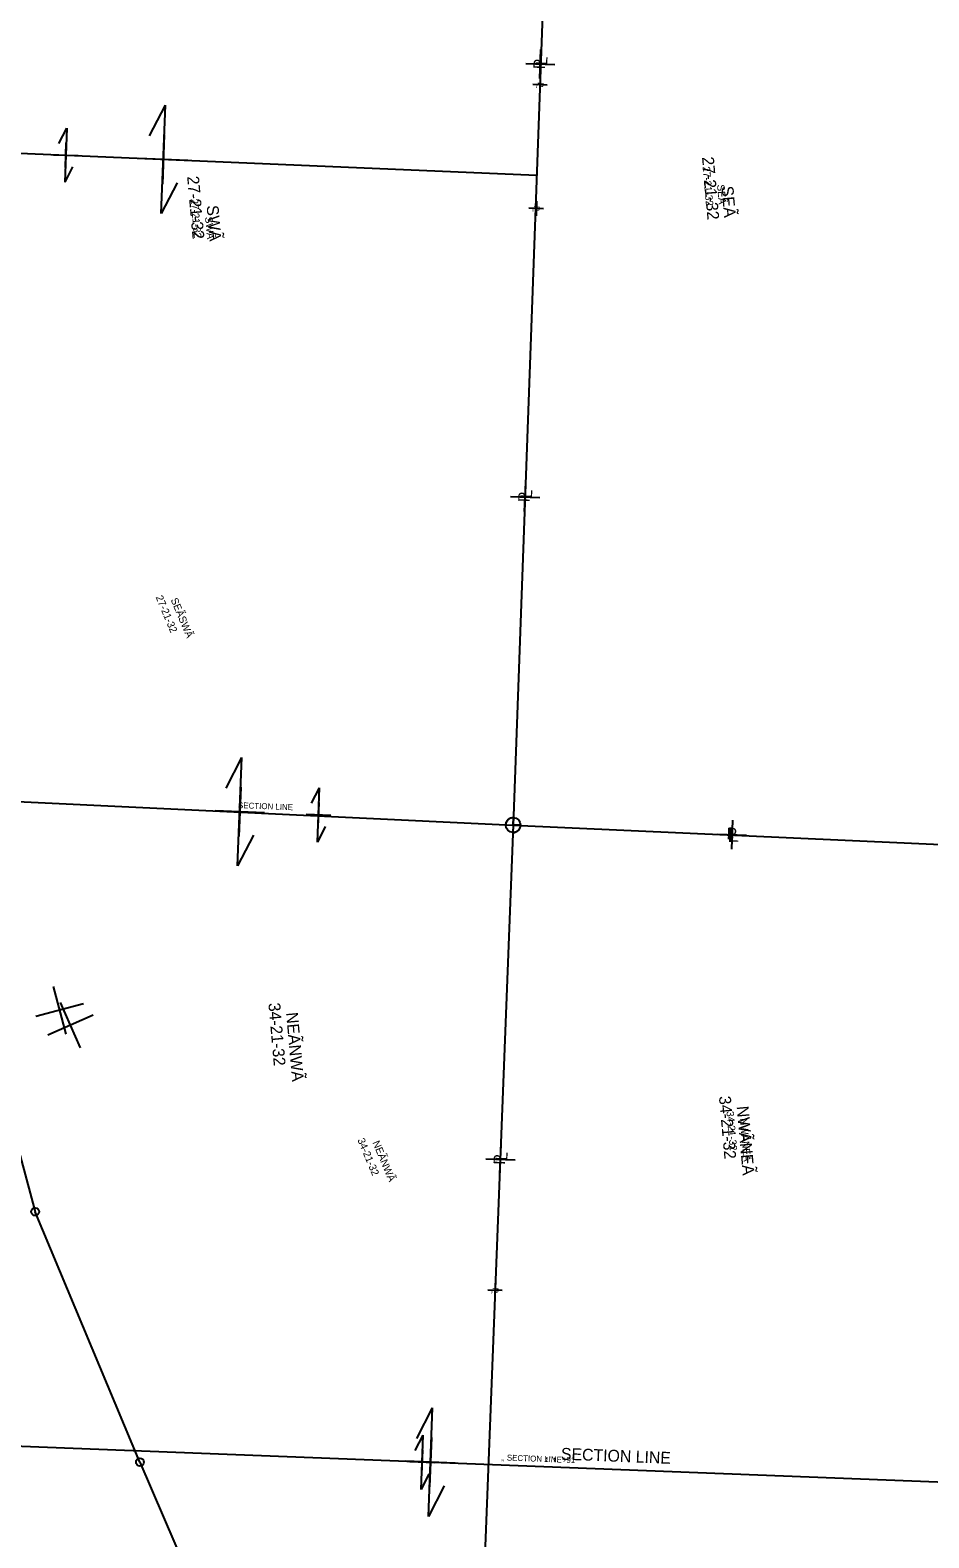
# Model space of a CAD drawing. Extents: x 2814293 to 2835768, y 121185 to 156337.
# Drawn here: x 2822119 to 2823940, y 124221 to 127276 of the extents above; entities that cross this region are included whole.
import ezdxf

# ---------------------------------------------------------------- set-up
doc = ezdxf.new("R2010")
doc.units = 0
for name, color, linetype in [('Default', 7, 'Continuous'), ('Photo-Retaining wall', 7, 'Continuous'), ('Roadway-Alignment notes', 7, 'Continuous'), ('Roadway-Edge of pavement', 7, 'Continuous'), ('Roadway-Edge of shoulder', 7, 'Continuous'), ('Roadway-Entrances', 7, 'Continuous'), ('Roadway-New rw', 7, 'Continuous'), ('Roadway-Safety', 7, 'Continuous'), ('Roadway-Walls', 7, 'Continuous'), ('Scratch-2', 7, 'Continuous'), ('Scratch-4', 7, 'Continuous'), ('Scratch-5', 7, 'Continuous'), ('Text-New rw label', 7, 'Continuous')]:
    doc.layers.add(name, color=color, linetype=linetype)

msp = doc.modelspace()

# ---------------------------------------------------------------- linework, layer by layer
at = {"layer": 'Default'}
for p, q in [((2822192, 125241.4), (2822166.3, 125338.1)), ((2822227.5, 125302.6), (2822130.8, 125276.9)), ((2822221.1, 125213.6), (2822181, 125305.3)), ((2822246.9, 125279.5), (2822155.2, 125239.4))]:
    msp.add_line(p, q, dxfattribs=at)
at = {"layer": 'Roadway-Edge of pavement'}
for p, q in [((2822177.4, 127046.3), (2822193.3, 127077.4)), ((2822193.3, 127077.4), (2822189.4, 126967.5)), ((2822190.5, 126997.5), (2822192.3, 127047.5)), ((2822166.4, 127023.4), (2822216.4, 127021.6)), ((2822191.4, 127022.5), (2822191.4, 127022.5)), ((2822205.3, 126998.7), (2822189.4, 126967.5)), ((2822689.5, 125709.4), (2822705.5, 125740.6)), ((2822701.3, 125630.6), (2822705.5, 125740.6)), ((2822704.4, 125710.6), (2822702.4, 125660.6)), ((2822728.4, 125684.6), (2822678.4, 125686.6)), ((2822703.4, 125685.6), (2822703.4, 125685.6)), ((2822717.3, 125661.8), (2822701.3, 125630.6)), ((2822899.5, 124397.6), (2822915.5, 124428.7)), ((2822911.2, 124318.8), (2822915.5, 124428.7)), ((2822914.3, 124398.8), (2822912.4, 124348.8)), ((2822938.3, 124372.8), (2822888.3, 124374.7)), ((2822913.3, 124373.8), (2822913.3, 124373.8)), ((2822927.2, 124349.9), (2822911.2, 124318.8))]:
    msp.add_line(p, q, dxfattribs=at)
at = {"layer": 'Roadway-Edge of shoulder'}
for p, q in [((2823152.1, 127177.9), (2823154.2, 127236.8)), ((2823123.7, 127208.4), (2823182.6, 127206.3)), ((2823121.2, 126300.5), (2823123.3, 126359.4)), ((2823092.8, 126331), (2823151.7, 126328.9)), ((2823542.3, 125674.8), (2823540, 125616)), ((2823511.7, 125646.6), (2823570.6, 125644.3)), ((2823071.2, 124958), (2823073.3, 125016.9)), ((2823042.8, 124988.5), (2823101.7, 124986.4))]:
    msp.add_line(p, q, dxfattribs=at)
at = {"layer": 'Roadway-Entrances'}
for p, q in [((2823193.2, 128299.4), (2823097.9, 125665)), ((2821815.2, 127038.4), (2823145.5, 126981.8)), ((2821766.3, 125728.5), (2823097.9, 125665)), ((2823097.9, 125665), (2822994.3, 122998.5)), ((2823097.9, 125665), (2825767.5, 125544.2)), ((2820377.3, 124472.9), (2825726, 124265.6))]:
    msp.add_line(p, q, dxfattribs=at)
at = {"layer": 'Roadway-New rw'}
for p, q in [((2822050.4, 125173.6), (2822129.4, 124881.4)), ((2822341.7, 124374.1), (2822129.4, 124881.4)), ((2822341.7, 124374.1), (2822651.5, 123652.3))]:
    msp.add_line(p, q, dxfattribs=at)
at = {"layer": 'Roadway-Walls'}
for p, q in [((2823167, 127164.4), (2823137.6, 127165.5)), ((2823152.8, 127179.7), (2823151.8, 127150.2)), ((2823145.2, 126929.3), (2823144.2, 126899.8)), ((2823159.4, 126914), (2823130, 126915.1)), ((2823522.6, 125646.1), (2823552, 125644.9)), ((2823537.9, 125660.2), (2823536.8, 125630.8)), ((2823075.9, 124721.5), (2823046.5, 124722.5)), ((2823061.7, 124736.7), (2823060.7, 124707.3))]:
    msp.add_line(p, q, dxfattribs=at)
at = {"layer": 'Scratch-2'}
for p, q in [((2822361.3, 127061.6), (2822393.3, 127123.8)), ((2822384.8, 126904), (2822393.3, 127123.8)), ((2822391, 127063.9), (2822387.1, 126964)), ((2822439, 127012), (2822339.1, 127015.9)), ((2822389.1, 127013.9), (2822389.1, 127013.9)), ((2822416.8, 126966.3), (2822384.8, 126904)), ((2822516.1, 125739.5), (2822548.1, 125801.8)), ((2822539.6, 125582), (2822548.1, 125801.8)), ((2822545.8, 125741.8), (2822541.9, 125641.9)), ((2822593.8, 125689.9), (2822493.9, 125693.8)), ((2822543.9, 125691.9), (2822543.9, 125691.9)), ((2822571.6, 125644.2), (2822539.6, 125582)), ((2822179.1, 125289.8), (2822179.1, 125289.8)), ((2822201.1, 125259.4), (2822201.1, 125259.4)), ((2822902.6, 124421.6), (2822934.6, 124483.8)), ((2822926.1, 124264), (2822934.6, 124483.8)), ((2822932.3, 124423.8), (2822928.4, 124323.9)), ((2822980.3, 124371.9), (2822880.4, 124375.8)), ((2822930.4, 124373.9), (2822930.4, 124373.9)), ((2822958.1, 124326.2), (2822926.1, 124264))]:
    msp.add_line(p, q, dxfattribs=at)
at = {"layer": 'Scratch-4'}
for p, q in [((2823082.9, 125665.5), (2823097.9, 125665)), ((2823097.9, 125665), (2823098.4, 125680)), ((2823097.9, 125665), (2823097.4, 125650)), ((2823112.9, 125664.5), (2823097.9, 125665))]:
    msp.add_line(p, q, dxfattribs=at)
msp.add_circle((2823097.9, 125665), 15, dxfattribs=at)
for start, end in [(88.1, 178.1), (268.1, 358.1)]:
    msp.add_arc((2823097.9, 125665), 15, start, end, dxfattribs=at)
at = {"layer": 'Text-New rw label'}
for centre in [(2822129.4, 124881.4), (2822341.7, 124374.1)]:
    msp.add_circle(centre, 8, dxfattribs=at)

# ---------------------------------------------------------------- texts
at = {"layer": 'Photo-Retaining wall'}
for s, rotation, p in [('27-21-32', 275.0693, (2823481.7, 126999)), ('SEÃ', 275.0693, (2823511.1, 126962.4)), ('27-21-32', 275.0693, (2822444.3, 126933.7)), ('SWÃ', 275.0693, (2822473.6, 126897.1)), ('27-21-32', 292.7163, (2822373.2, 126126.9)), ('SEÃSWÃ', 292.7163, (2822403.6, 126121.7)), ('34-21-32', 275.0693, (2823530, 125084.6)), ('NWÃNEÃ', 275.0693, (2823557.3, 125070.3)), ('34-21-32', 292.7163, (2822782.1, 125026.9)), ('NEÃNWÃ', 292.7163, (2822812.5, 125021.7))]:
    msp.add_text(s, height=15, rotation=rotation, dxfattribs=at).set_placement(p)
at = {"layer": 'Roadway-Alignment notes'}
for s, p in [('27-21-32', (2823480.5, 127018.4)), ('27-21-32', (2822437.2, 126979.3)), ('SEÃ', (2823519.9, 126959.1)), ('SWÃ', (2822476.6, 126920.1)), ('34-21-32', (2822601.8, 125303.9)), ('NEÃNWÃ', (2822637.7, 125284.6)), ('34-21-32', (2823514.8, 125115.1)), ('NWÃNEÃ', (2823550.8, 125094.7))]:
    msp.add_text(s, height=24, rotation=275.0693, dxfattribs=at).set_placement(p)
at = {"layer": 'Roadway-Edge of shoulder'}
for s, rotation, p in [('P', 87.9775, (2823162.4, 127196.3)), ('L', 87.9775, (2823167, 127204.2)), ('P', 87.9775, (2823131.5, 126319)), ('L', 87.9775, (2823136.1, 126326.8)), ('P', 357.7804, (2823530.1, 125636.2)), ('L', 357.7804, (2823537.9, 125631.6)), ('P', 87.9775, (2823081.5, 124976.4)), ('L', 87.9775, (2823086.1, 124984.3))]:
    msp.add_text(s, height=23.6, rotation=rotation, dxfattribs=at).set_placement(p)
at = {"layer": 'Roadway-Safety'}
for s, p in [('SECTION LINE', (2822540.2, 125699.3)), ('‚‚ SECTION LINE+91', (2823073.4, 124377.7))]:
    msp.add_text(s, height=12, rotation=357.7804, dxfattribs=at).set_placement(p)
at = {"layer": 'Roadway-Walls'}
for s, rotation, p in [('L', 267.9775, (2823145.4, 127166.6)), ('P', 267.9775, (2823147.7, 127170.5)), ('P', 267.9775, (2823140.1, 126920)), ('L', 267.9775, (2823137.8, 126916.1)), ('P', 357.7804, (2823531.8, 125640.9)), ('L', 357.7804, (2823535.7, 125638.6)), ('L', 267.9775, (2823054.3, 124723.6)), ('P', 267.9775, (2823056.6, 124727.5))]:
    msp.add_text(s, height=11.8, rotation=rotation, dxfattribs=at).set_placement(p)
at = {"layer": 'Scratch-5'}
msp.add_text('‚ ‚ SECTION LINE', height=24, rotation=357.7804, dxfattribs=at).set_placement((2823162.3, 124380.3))

doc.saveas('drawing.dxf')
